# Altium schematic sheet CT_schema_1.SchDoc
size 505 x 488 mm
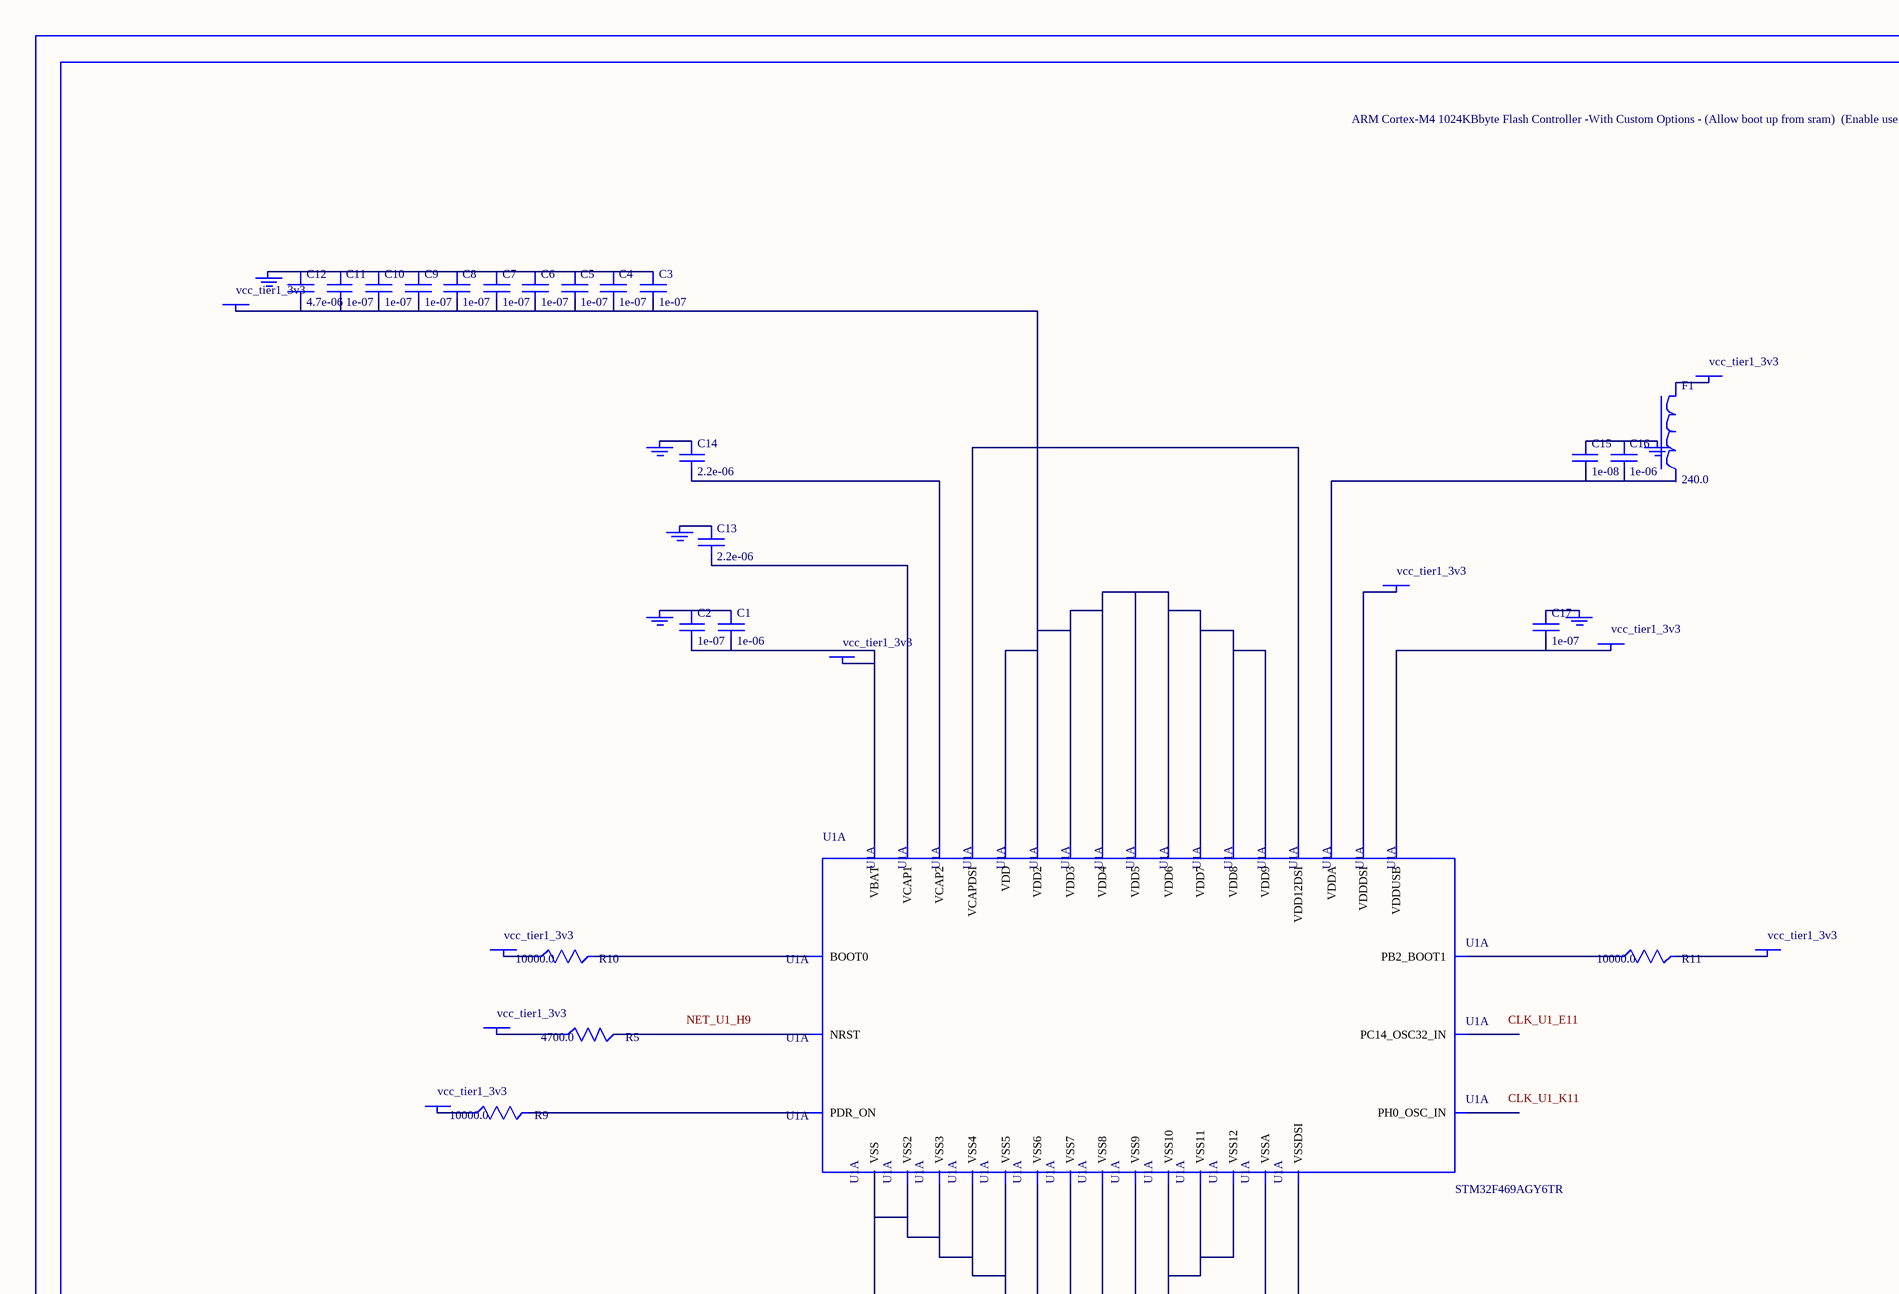
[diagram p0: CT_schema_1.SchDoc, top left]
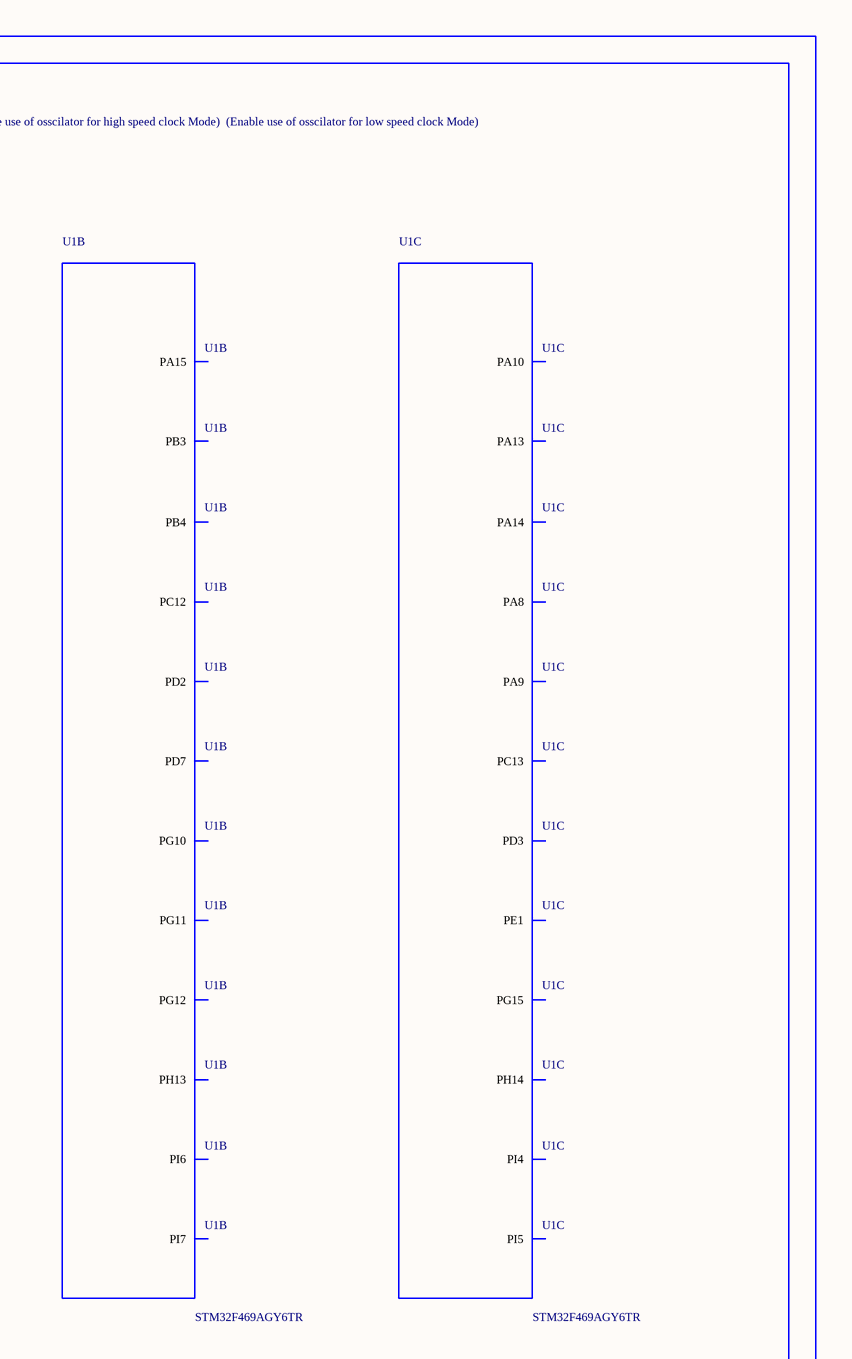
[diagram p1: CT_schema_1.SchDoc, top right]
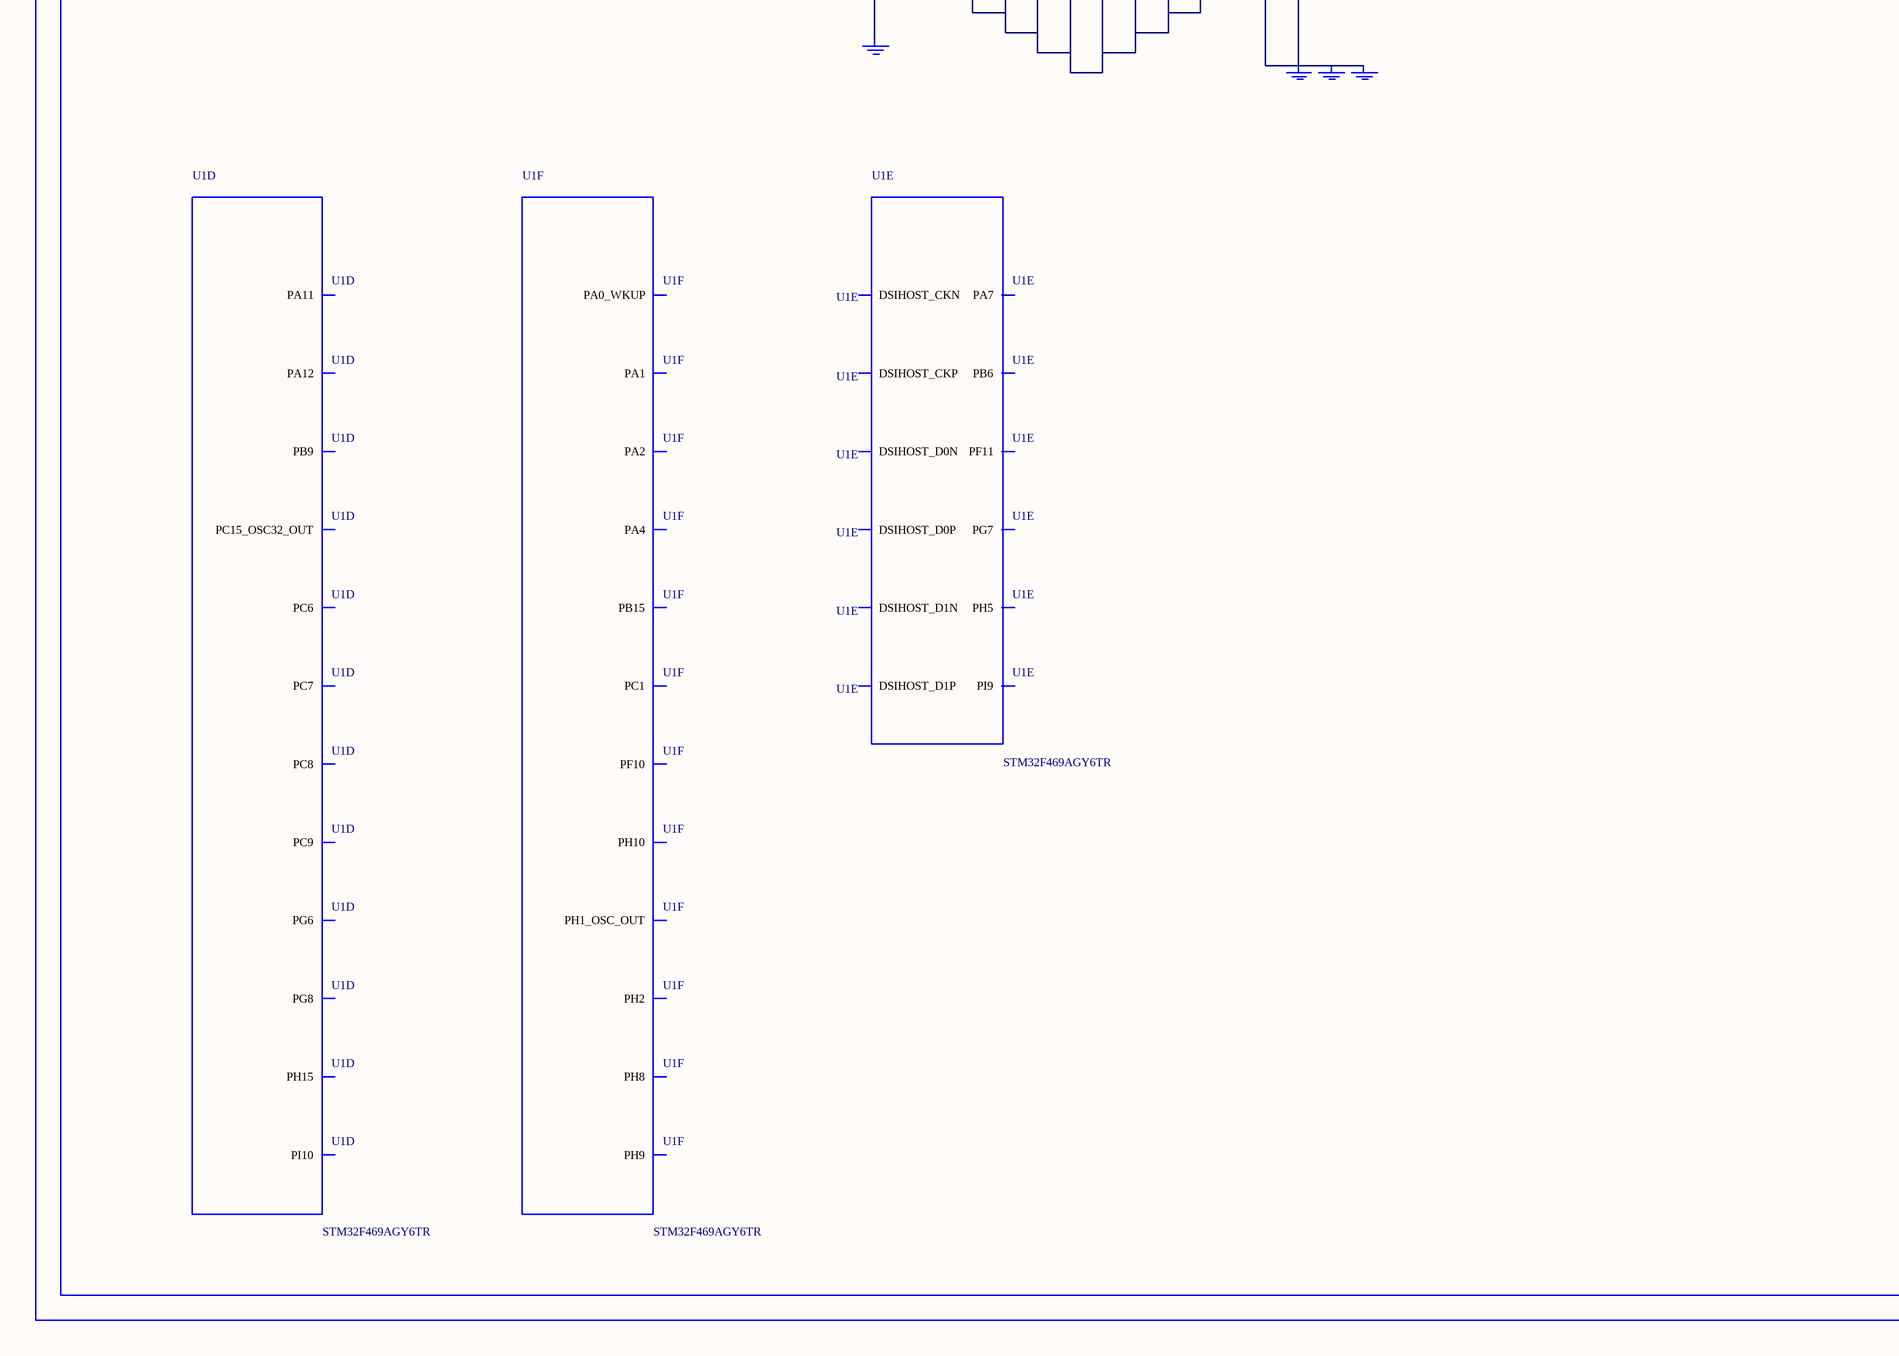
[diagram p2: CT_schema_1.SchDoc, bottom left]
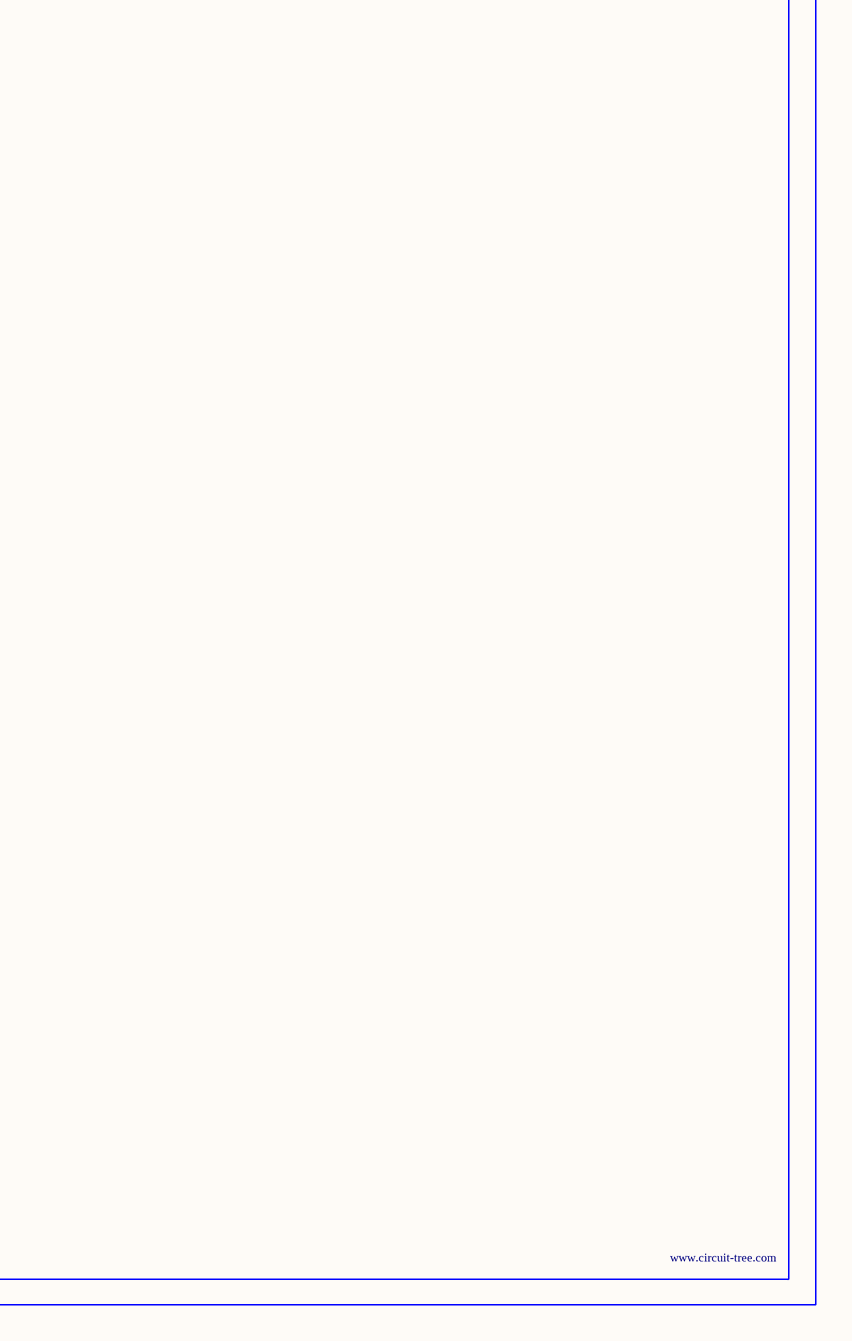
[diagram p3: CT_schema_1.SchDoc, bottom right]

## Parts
BORDER0  (no value)
C1  1e-06  [C0603]
C2  1e-07  [C0603]
C3  1e-07  [C0603]
C4  1e-07  [C0603]
C5  1e-07  [C0603]
C6  1e-07  [C0603]
C7  1e-07  [C0603]
C8  1e-07  [C0603]
C9  1e-07  [C0603]
C10  1e-07  [C0603]
C11  1e-07  [C0603]
C12  4.7e-06  [C0603]
C13  2.2e-06  [C0603]
C14  2.2e-06  [C0603]
C15  1e-08  [C0603]
C16  1e-06  [C0603]
C17  1e-07  [C0603]
F1  240.0  [L0603]
GND_INSTANCE_0_0  (no value)
GND_INSTANCE_0_1  (no value)
GND_INSTANCE_0_2  (no value)
GND_INSTANCE_0_3  (no value)
GND_INSTANCE_0_4  (no value)
GND_INSTANCE_0_5  (no value)
GND_INSTANCE_0_6  (no value)
GND_INSTANCE_0_7  (no value)
GND_INSTANCE_0_8  (no value)
GND_INSTANCE_0_9  (no value)
POWER_INSTANCE_0_0  vcc_tier1_3v3
POWER_INSTANCE_0_1  vcc_tier1_3v3
POWER_INSTANCE_0_2  vcc_tier1_3v3
POWER_INSTANCE_0_3  vcc_tier1_3v3
POWER_INSTANCE_0_4  vcc_tier1_3v3
POWER_INSTANCE_0_5  vcc_tier1_3v3
POWER_INSTANCE_0_6  vcc_tier1_3v3
POWER_INSTANCE_0_7  vcc_tier1_3v3
POWER_INSTANCE_0_8  vcc_tier1_3v3
R5  4700.0  [R0603]
R9  10000.0  [R0603]
R10  10000.0  [R0603]
R11  10000.0  [R0603]
U1  STM32F469AGY6TR  [WLCSP168]  (parts A,B,C,D,E,F of 13)

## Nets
NetC1_1: C1.1 C2.1 GND_INSTANCE_0_0.0(GND)
NetC1_2: C1.2 C2.2 POWER_INSTANCE_0_0.0(PWR) U1.C12(VBAT)
NetC3_1: C3.1 C4.1 C5.1 C6.1 C7.1 C8.1 C9.1 C10.1 C11.1 C12.1 GND_INSTANCE_0_2.0(GND)
NetC3_2: C3.2 C4.2 C5.2 C6.2 C7.2 C8.2 C9.2 C10.2 C11.2 C12.2 POWER_INSTANCE_0_2.0(PWR) U1.A7(VDD2) U1.A11(VDD) U1.B5(VDD3) U1.C2(VDD4) U1.G11(VDD5) U1.J12(VDD6) U1.P3(VDD8) U1.P8(VDD9) U1.P12(VDD7)
NetC13_1: C13.1 GND_INSTANCE_0_3.0(GND)
NetC13_2: C13.2 U1.N4(VCAP1)
NetC14_1: C14.1 GND_INSTANCE_0_4.0(GND)
NetC14_2: C14.2 U1.D2(VCAP2)
NetC15_1: C15.1 C16.1 GND_INSTANCE_0_1.0(GND)
NetC15_2: C15.2 C16.2 U1.M12(VDDA)
NetC17_1: C17.1 GND_INSTANCE_0_5.0(GND)
NetC17_2: C17.2 POWER_INSTANCE_0_4.0(PWR) U1.F1(VDDUSB)
NetF1_1: F1.1 POWER_INSTANCE_0_1.0(PWR)
NetGND_INSTANCE_0_6_0: GND_INSTANCE_0_6.0(GND) GND_INSTANCE_0_7.0(GND) GND_INSTANCE_0_8.0(GND) U1.H1(VSSDSI) U1.L11(VSSA)
NetGND_INSTANCE_0_9_0: GND_INSTANCE_0_9.0(GND) U1.A4(VSS) U1.B7(VSS3) U1.B10(VSS2) U1.C1(VSS4) U1.F2(VSS6) U1.F12(VSS5) U1.H7(VSS7) U1.J11(VSS8) U1.M1(VSS9) U1.N8(VSS11) U1.N11(VSS10) U1.P4(VSS12)
NetPOWER_INSTANCE_0_3_0: POWER_INSTANCE_0_3.0(PWR) R9.1
NetPOWER_INSTANCE_0_5_0: POWER_INSTANCE_0_5.0(PWR) R10.1
NetPOWER_INSTANCE_0_6_0: POWER_INSTANCE_0_6.0(PWR) R11.2
NetPOWER_INSTANCE_0_7_0: POWER_INSTANCE_0_7.0(PWR) U1.L1(VDDDSI)
NetPOWER_INSTANCE_0_8_0: POWER_INSTANCE_0_8.0(PWR) R5.1
NetR5_2: R5.2 U1.H9(NRST)
NetR9_2: R9.2 U1.D9(PDR_ON)
NetR10_2: R10.2 U1.F8(BOOT0)
NetR11_1: R11.1 U1.P9(PB2_BOOT1)
NetU1_K1: U1.K1(VCAPDSI) U1.K2(VDD12DSI)

Not connected (* = marked no-connect by the designer): F1 2; U1 A2(PA15) A5(PD7) A6(PG12) A8(PB3) A12(PI7) B1(PH13) B6(PG11) B11(PI6) C4(PC12) C5(PD2) C7(PG10) C8(PB4) C9(PE1) C10(PI5) D1(PA13) D3(PH14) D4(PA14) D6(PD3) D8(PG15) D10(PI4) D12(PC13) E1(PA8) E2(PA9) E3(PA10) E4(PH15) E9(PB9) E11(PC14_OSC32_IN) E12(PC15_OSC32_OUT) F3(PC6) F4(PC8) F5(PC9) F6(PA12) F7(PA11) F10(PI10) G3(PG6) G6(PG8) G7(PC7) G8(PB6) G9(PI9) H2(DSIHOST_D1N) H3(DSIHOST_D1P) H6(PG7) J1(DSIHOST_CKP) J2(DSIHOST_CKN) J3(DSIHOST_D0N) J8(PA7) K3(DSIHOST_D0P) K7(PF11) K8(PH5) K9(PA1) K10(PF10) K11(PH0_OSC_IN) K12(PH1_OSC_OUT) L5(PH9) L9(PA2) L10(PA0_WKUP) L12(PC1) M4(PH10) M5(PH8) M9(PA4) M11(PH2) N2(PB15)

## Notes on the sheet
- Labels drawn without touching a wire or pin: CLK_U1_E11, CLK_U1_K11, NET_U1_H9

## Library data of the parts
BORDER0 = BORDER_PAGE0
C1 C16 = C0603C105K3RACTU
C2-C11 C17 = 06035C104K4Z2A
C12 = GRM188R6YA475KE15D
C13 C14 = C0603C225K8RACTU
C15 = 06035C103K4Z2A
F1 = Z0603C241ASMST
GND_INSTANCE_0_0-GND_INSTANCE_0_9 = GND
POWER_INSTANCE_0_0-POWER_INSTANCE_0_8 = PWR
R5 = RC0603JR-074K7L
R9-R11 = RC0603JR-0710KL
